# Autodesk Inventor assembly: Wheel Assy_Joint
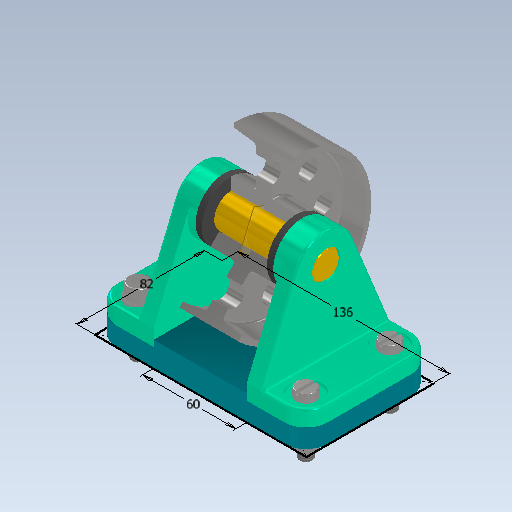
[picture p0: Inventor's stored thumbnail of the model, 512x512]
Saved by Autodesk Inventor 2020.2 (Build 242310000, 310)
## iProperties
Created: 2020-01
Part Number: Wheel Assy_Joint
Document SubType Name: Assembly
Designer: thira
Author: thira
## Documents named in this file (11)
- C:\Users\thira\OneDrive\เดสก์ท็อป\INV-01 Intro to Modeling_2020\Wheel Assem Final V1\Wheel Assy_Joint.iam
- C:\Users\thira\OneDrive\เดสก์ท็อป\INV-01 Intro to Modeling_2020\Wheel Assem Final V1\Plate V1.ipt
- C:\Users\thira\OneDrive\เดสก์ท็อป\INV-01 Intro to Modeling_2020\Wheel Assem Final V1\Shaft V1.ipt
- C:\Users\thira\OneDrive\เดสก์ท็อป\INV-01 Intro to Modeling_2020\Wheel Assem Final V1\Support Wheel V1.ipt
- C:\Users\thira\OneDrive\เดสก์ท็อป\INV-01 Intro to Modeling_2020\Wheel Assem Final V1\Wheel V1.ipt
- C:\Users\thira\OneDrive\เดสก์ท็อป\INV-01 Intro to Modeling_2020\Wheel Assem Final V1\Seal.ipt
- C:\Users\thira\OneDrive\เอกสาร\Inventor\Content Center Files\R2020\en-US\ISO 1207(2)\ISO 1207 - M8 x 35.ipt
- C:\Users\thira\OneDrive\เอกสาร\Inventor\Content Center Files\R2020\en-US\ISO 7089\ISO 7089 - 10 - 140 HV(1).ipt
- C:\Users\thira\OneDrive\เอกสาร\Inventor\Content Center Files\R2020\en-US\ISO 4032(2)\ISO 4032 - M8 - ISO.ipt
- C:\Users\thira\OneDrive\เดสก์ท็อป\INV-01 Intro to Modeling_2020\Wheel Assem Final V1\Wheel Assy_Joint\Design Accelerator\Bolted Connection1.iam
- C:\Users\thira\OneDrive\เดสก์ท็อป\INV-01 Intro to Modeling_2020\Wheel Assem Final V1\Wheel Assy_Joint\Design Accelerator\Bolted Connection2.iam
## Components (17 placed, 9 different names)
1. Plate V1:1 — Rigid:1, Mate:1, Flush:1, Flush:2, Angle:1
2. Shaft V1:1 — Cylindrical:1, Planar:1, Cylindrical:2, Planar:2, Mate:2, Rotational:1
3. Support Wheel V1:1 — Rigid:1, Cylindrical:1, Planar:1, Flush:3, Flush:4, Mate:12, Mate:13, Mate:14, Mate:15
4. Wheel V1:1 — Cylindrical:2, Planar:2, Angle:1, Rotational:1
5. Support Wheel V1:2 — Mate:1, Flush:1, Flush:2, Mate:3
6. Seal:1 — Flush:3, Flush:4
7. Seal:2 — Mate:2, Mate:3
8. ISO 1207 M8 x 35:1
9. ISO 1207 M8 x 35:2
10. ISO 7089 10:1 — Mate:11
11. ISO 7089 10:2
12. ISO 7089 10:3 — Mate:9
13. ISO 7089 10:4
14. ISO 4032 M8:1 — Mate:9
15. ISO 4032 M8:2 — Mate:11
16. Bolted Connection:1 [sub-assembly] — Mate:12, Mate:13
17. Bolted Connection:2 [sub-assembly] — Mate:14, Mate:15
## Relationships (20: Mate 9, Flush 4, CylindricalJoint 2, PlanarJoint 2, WeldJoint 1, Angle 1, RevoluteJoint 1)
- Rigid:1 [WeldJoint]: Plate V1:1 ↔ Support Wheel V1:1
- Mate:1: Plate V1:1 ↔ Support Wheel V1:2
- Flush:1: Plate V1:1 ↔ Support Wheel V1:2
- Flush:2: Plate V1:1 ↔ Support Wheel V1:2
- Cylindrical:1: Shaft V1:1 ↔ Support Wheel V1:1
- Planar:1: Shaft V1:1 ↔ Support Wheel V1:1
- Cylindrical:2: Shaft V1:1 ↔ Wheel V1:1
- Planar:2: Shaft V1:1 ↔ Wheel V1:1
- Flush:3: Support Wheel V1:1 ↔ Seal:1
- Flush:4: Support Wheel V1:1 ↔ Seal:1
- Mate:2: Shaft V1:1 ↔ Seal:2
- Mate:3: Support Wheel V1:2 ↔ Seal:2
- Angle:1: Plate V1:1 ↔ Wheel V1:1
- Rotational:1 [RevoluteJoint]: Shaft V1:1 ↔ Wheel V1:1
- Mate:9: ISO 7089 10:3 ↔ ISO 4032 M8:1
- Mate:11: ISO 7089 10:1 ↔ ISO 4032 M8:2
- Mate:12: Support Wheel V1:1 ↔ Bolted Connection:1
- Mate:13: Support Wheel V1:1 ↔ Bolted Connection:1
- Mate:14: Support Wheel V1:1 ↔ Bolted Connection:2
- Mate:15: Support Wheel V1:1 ↔ Bolted Connection:2
